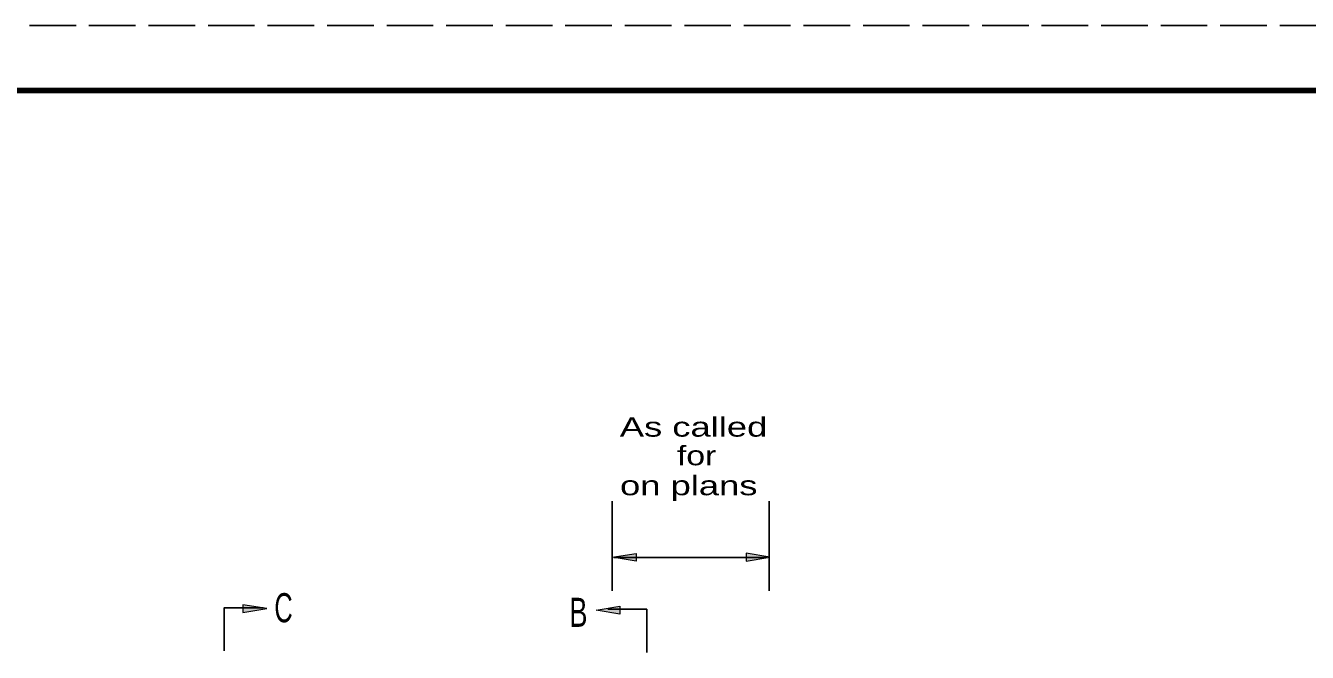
# Model space of a CAD drawing. Extents: x 75.6 to 110.9, y 28 to 50.
# Drawn here: x 92.93 to 102.83, y 45.14 to 49.98 of the extents above; entities that cross this region are included whole.
import ezdxf
from ezdxf.enums import TextEntityAlignment as Align

# ---------------------------------------------------------------- set-up
doc = ezdxf.new("R2010")
doc.units = 0
doc.header["$LTSCALE"] = 0.06
doc.linetypes.add('LONG_DASHED', pattern=[7.5, 6, -1.5])
doc.layers.add('1', color=7, linetype='Continuous', lineweight=25)
doc.layers.add('3', color=7, linetype='Continuous', lineweight=13)

msp = doc.modelspace()

# ---------------------------------------------------------------- hatches: boundary and pattern name
at = {"layer": '3'}
for points in [[(97.64658, 45.90217), (97.64658, 45.84067), (97.46192, 45.8715), (97.46192, 45.8715)], [(98.49667, 45.90225), (98.49667, 45.84075), (98.68125, 45.87158), (98.68125, 45.87158)], [(94.60817, 45.50533), (94.60817, 45.44392), (94.79275, 45.47467), (94.79275, 45.47467)], [(97.52233, 45.49383), (97.52233, 45.43233), (97.33775, 45.46308), (97.33775, 45.46308)]]:
    msp.add_hatch(color=256, dxfattribs=at).paths.add_polyline_path(points)

# ---------------------------------------------------------------- linework, layer by layer
at = {"layer": '1', "linetype": 'LONG_DASHED'}
msp.add_line((110.8, 49.97992), (75.6, 49.97992), dxfattribs=at)
at = {"layer": '1', "lineweight": 158}
msp.add_line((110.71667, 49.47992), (78.21667, 49.47992), dxfattribs=at)
at = {"layer": '1'}
for p, q in [((97.46292, 45.6135), (97.46292, 46.30575)), ((98.67558, 45.6135), (98.67558, 46.30575)), ((97.475, 45.86942), (98.65725, 45.86942))]:
    msp.add_line(p, q, dxfattribs=at)
for points in [[(94.76692, 45.48117), (94.4645, 45.48117), (94.4645, 45.1485)], [(97.42742, 45.46958), (97.72983, 45.46958), (97.72983, 45.13692)]]:
    msp.add_lwpolyline(points, dxfattribs=at)
at = {"layer": '3'}
for points in [[(97.64658, 45.90217), (97.64658, 45.84067), (97.46192, 45.8715), (97.46192, 45.8715)], [(98.49667, 45.90225), (98.49667, 45.84075), (98.68125, 45.87158), (98.68125, 45.87158)], [(94.60817, 45.50533), (94.60817, 45.44392), (94.79275, 45.47467), (94.79275, 45.47467)], [(97.52233, 45.49383), (97.52233, 45.43233), (97.33775, 45.46308), (97.33775, 45.46308)]]:
    msp.add_lwpolyline(points, close=True, dxfattribs=at)

# ---------------------------------------------------------------- texts
at = {"layer": '1'}
for s, height, width, p in [('As called', 0.15, 1.4, (98.09083, 46.80392)), ('for', 0.15, 1.3, (98.11458, 46.58275)), ('on plans', 0.15, 1.4, (98.05371, 46.35108)), ('C', 0.225, 0.65, (94.923, 45.3695)), ('B', 0.225, 0.7, (97.201, 45.33408))]:
    msp.add_text(s, height=height, dxfattribs=dict(at, width=width)).set_placement(p, align=Align.CENTER)

doc.saveas('drawing.dxf')
